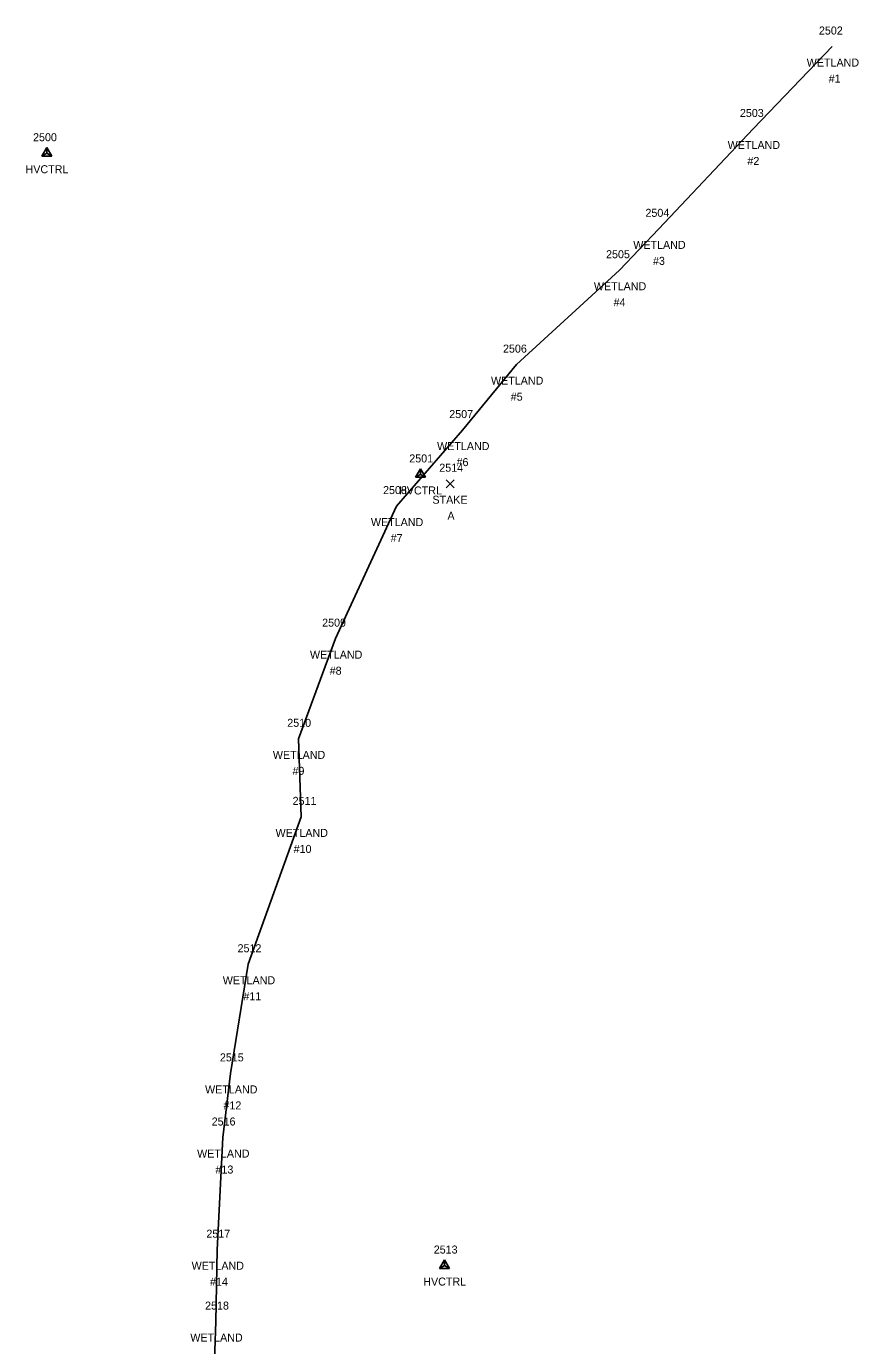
# Model space of a CAD drawing. Extents: x 1885914 to 1887218, y 756253 to 760620.
# Drawn here: x 1886840.7 to 1887048.5, y 760290.2 to 760619.8 of the extents above; entities that cross this region are included whole.
import ezdxf

# ---------------------------------------------------------------- set-up
doc = ezdxf.new("R2010")
doc.units = 0
for name, color, linetype in [('C_A', 7, 'Continuous'), ('C_C', 7, 'Continuous'), ('C_I', 7, 'Continuous'), ('CPSM', 7, 'Continuous'), ('E_TIC', 7, 'Continuous'), ('L_A', 7, 'Continuous'), ('L_C', 7, 'Continuous'), ('L_I', 7, 'Continuous'), ('LWET', 7, 'Continuous')]:
    doc.layers.add(name, color=color, linetype=linetype)

msp = doc.modelspace()

# ---------------------------------------------------------------- linework, layer by layer
at = {"layer": 'CPSM'}
for p, q in [((1886844.53, 760587.43), (1886845.78, 760589.6)), ((1886844.53, 760587.43), (1886845.78, 760588.15)), ((1886844.53, 760587.43), (1886847.03, 760587.43)), ((1886847.03, 760587.43), (1886845.78, 760589.6)), ((1886845.78, 760588.15), (1886845.78, 760589.6)), ((1886845.78, 760588.15), (1886845.78, 760588.15)), ((1886845.78, 760588.15), (1886847.03, 760587.43)), ((1886937.8, 760507.18), (1886939.05, 760509.34)), ((1886940.3, 760507.18), (1886939.05, 760509.34)), ((1886939.05, 760507.9), (1886939.05, 760509.34)), ((1886937.8, 760507.18), (1886939.05, 760507.9)), ((1886937.8, 760507.18), (1886940.3, 760507.18)), ((1886939.05, 760507.9), (1886939.05, 760507.9)), ((1886939.05, 760507.9), (1886940.3, 760507.18)), ((1886943.84, 760309.52), (1886945.09, 760311.68)), ((1886943.84, 760309.52), (1886945.09, 760310.24)), ((1886946.34, 760309.52), (1886945.09, 760311.68)), ((1886945.09, 760310.24), (1886945.09, 760311.68)), ((1886945.09, 760310.24), (1886945.09, 760310.24)), ((1886945.09, 760310.24), (1886946.34, 760309.52)), ((1886943.84, 760309.52), (1886946.34, 760309.52))]:
    msp.add_line(p, q, dxfattribs=at)
at = {"layer": 'E_TIC'}
for points in [[(1886945.47, 760504.58), (1886947.47, 760506.58)], [(1886947.47, 760504.58), (1886945.47, 760506.58)]]:
    msp.add_lwpolyline(points, dxfattribs=at)
at = {"layer": 'LWET'}
msp.add_lwpolyline([(1887041.89, 760614.81), (1887022.16, 760594.21), (1886998.58, 760569.26), (1886988.75, 760558.92), (1886963.07, 760535.33), (1886949.6, 760518.98), (1886933.08, 760499.99), (1886917.87, 760466.87), (1886908.6, 760441.84), (1886909.29, 760422.34), (1886896.1, 760385.52), (1886891.69, 760358.25), (1886889.7, 760342.23), (1886888.33, 760314.2), (1886888.01, 760296.24), (1886887.25, 760274.28), (1886889.16, 760259.72), (1886886.34, 760246.96), (1886879.04, 760229.05), (1886869.75, 760207.75), (1886856.31, 760188.01)], dxfattribs=at)

# ---------------------------------------------------------------- texts
at = {"layer": 'C_A'}
for s, p in [('HVCTRL', (1886840.48, 760583.15)), ('HVCTRL', (1886933.74, 760502.9)), ('STAKE', (1886942.06, 760500.58)), ('HVCTRL', (1886939.78, 760305.24))]:
    msp.add_text(s, height=2, dxfattribs=at).set_placement(p)
at = {"layer": 'C_C'}
msp.add_text('A', height=2, dxfattribs=at).set_placement((1886945.81, 760496.58))
at = {"layer": 'C_I'}
for s, p in [('2500', (1886842.36, 760591.15)), ('2501', (1886936.28, 760510.9)), ('2514', (1886943.77, 760508.58)), ('2513', (1886942.39, 760313.24))]:
    msp.add_text(s, height=2, dxfattribs=at).set_placement(p)
at = {"layer": 'L_A'}
for p in [(1887035.5, 760609.81), (1887015.77, 760589.21), (1886992.2, 760564.26), (1886982.36, 760553.92), (1886956.68, 760530.33), (1886943.22, 760513.98), (1886926.7, 760494.99), (1886911.49, 760461.87), (1886902.22, 760436.84), (1886902.9, 760417.34), (1886889.72, 760380.52), (1886885.3, 760353.25), (1886883.31, 760337.23), (1886881.94, 760309.2), (1886881.62, 760291.24)]:
    msp.add_text('WETLAND', height=2, dxfattribs=at).set_placement(p)
at = {"layer": 'L_C'}
for s, p in [('#1', (1887040.99, 760605.81)), ('#2', (1887020.69, 760585.21)), ('#3', (1886997.12, 760560.26)), ('#4', (1886987.28, 760549.92)), ('#5', (1886961.61, 760526.33)), ('#6', (1886948.08, 760509.98)), ('#7', (1886931.62, 760490.99)), ('#8', (1886916.41, 760457.87)), ('#9', (1886907.13, 760432.84)), ('#10', (1886907.41, 760413.34)), ('#11', (1886894.87, 760376.52)), ('#12', (1886889.89, 760349.25)), ('#13', (1886887.9, 760333.23)), ('#14', (1886886.53, 760305.2))]:
    msp.add_text(s, height=2, dxfattribs=at).set_placement(p)
at = {"layer": 'L_I'}
for s, p in [('2502', (1887038.55, 760617.81)), ('2503', (1887018.82, 760597.21)), ('2504', (1886995.24, 760572.26)), ('2505', (1886985.41, 760561.92)), ('2506', (1886959.68, 760538.33)), ('2507', (1886946.26, 760521.98)), ('2508', (1886929.74, 760502.99)), ('2509', (1886914.53, 760469.87)), ('2510', (1886905.82, 760444.84)), ('2511', (1886907.16, 760425.34)), ('2512', (1886893.41, 760388.52)), ('2515', (1886889, 760361.25)), ('2516', (1886886.95, 760345.23)), ('2517', (1886885.63, 760317.2)), ('2518', (1886885.31, 760299.24))]:
    msp.add_text(s, height=2, dxfattribs=at).set_placement(p)

doc.saveas('drawing.dxf')
